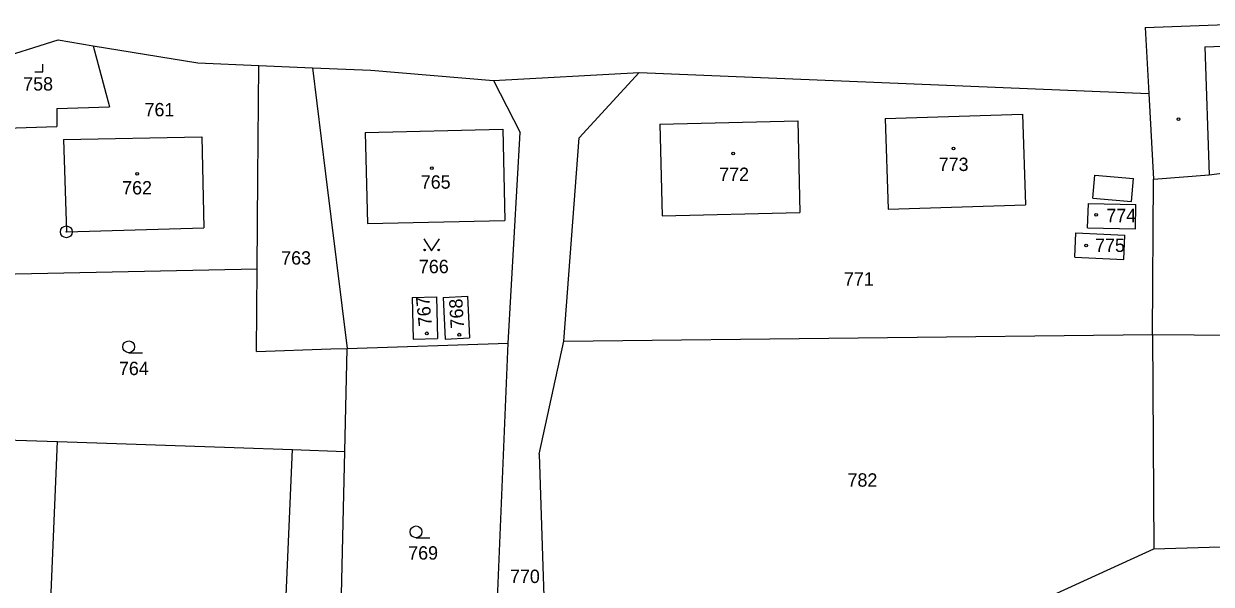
# Model space of a CAD drawing. Extents: x -779596 to -776743, y -1030330 to -1024513.
# Drawn here: x -778089.5 to -777938.4, y -1025062.8 to -1024991.4 of the extents above; entities that cross this region are included whole.
import ezdxf

# ---------------------------------------------------------------- set-up
doc = ezdxf.new("R2010")
doc.units = 0
for name, color, linetype in [('hranice parcel', 7, 'Continuous'), ('hranice vnitřní', 7, 'Continuous'), ('kultura', 7, 'Continuous'), ('Kód', 7, 'Continuous'), ('č_pacel stav_', 7, 'Continuous'), ('č_parcel poz_', 7, 'Continuous')]:
    doc.layers.add(name, color=color, linetype=linetype)

msp = doc.modelspace()

# ---------------------------------------------------------------- linework, layer by layer
at = {"layer": 'hranice parcel'}
for points in [[(-777946.82, -1024991.9), (-777934.22, -1024991.43)], [(-777946.82, -1024991.9), (-777946.37, -1025000.32)], [(-778093.81, -1024996.18), (-778085.15, -1024993.48)], [(-778085.15, -1024993.48), (-778080.71, -1024994.22)], [(-778080.71, -1024994.22), (-778067.37, -1024996.42)], [(-778080.71, -1024994.22), (-778078.6, -1025002)], [(-778067.37, -1024996.42), (-778059.62, -1024996.75)], [(-778059.74, -1025011.01), (-778059.62, -1024996.75)], [(-778059.62, -1024996.75), (-778052.78, -1024997.04)], [(-778052.78, -1024997.04), (-778045.34, -1024997.35)], [(-778052.78, -1024997.04), (-778051.11, -1025010.51)], [(-778045.34, -1024997.35), (-778029.75, -1024998.66)], [(-778029.75, -1024998.66), (-778011.2, -1024997.65)], [(-778018.85, -1025005.96), (-778011.2, -1024997.65)], [(-778011.2, -1024997.65), (-777946.37, -1025000.32)], [(-778029.75, -1024998.66), (-778026.36, -1025005.29)], [(-777946.37, -1025000.32), (-777945.78, -1025011.19)], [(-778085.3, -1025002.2), (-778078.6, -1025002)], [(-778085.3, -1025002.2), (-778085.3, -1025004.5)], [(-778008.58, -1025004.22), (-777991.03, -1025003.8)], [(-778008.58, -1025004.22), (-778008.3, -1025015.87)], [(-777991.03, -1025003.8), (-777990.75, -1025015.45)], [(-777979.91, -1025003.49), (-777962.42, -1025002.93)], [(-777979.91, -1025003.49), (-777979.54, -1025015.04)], [(-777962.42, -1025002.93), (-777962.05, -1025014.49)], [(-778091.8, -1025004.7), (-778085.3, -1025004.5)], [(-778084.45, -1025006.17), (-778066.85, -1025005.82)], [(-778066.85, -1025005.82), (-778066.62, -1025017.38)], [(-778046.07, -1025005.26), (-778028.56, -1025004.86)], [(-778046.07, -1025005.26), (-778045.8, -1025016.87)], [(-778028.56, -1025004.86), (-778028.29, -1025016.47)], [(-778027.87, -1025032.06), (-778026.36, -1025005.29)], [(-778084.45, -1025006.17), (-778084.1, -1025017.91)], [(-778020.82, -1025031.82), (-778018.85, -1025005.96)], [(-777938.7, -1025010.66), (-777923.12, -1025008.6)], [(-778059.83, -1025022.61), (-778059.74, -1025011.01)], [(-778051.11, -1025010.51), (-778048.36, -1025032.75)], [(-777945.88, -1025030.99), (-777945.78, -1025011.19)], [(-777945.78, -1025011.19), (-777938.7, -1025010.66)], [(-777979.54, -1025015.04), (-777962.05, -1025014.49)], [(-777954.16, -1025017.4), (-777954.02, -1025014.31)], [(-777954.02, -1025014.31), (-777948.02, -1025014.44)], [(-777948.05, -1025017.53), (-777948.02, -1025014.44)], [(-778045.8, -1025016.87), (-778028.29, -1025016.47)], [(-778008.3, -1025015.87), (-777990.75, -1025015.45)], [(-778084.1, -1025017.91), (-778066.62, -1025017.38)], [(-777954.16, -1025017.4), (-777948.05, -1025017.53)], [(-777955.79, -1025021.12), (-777955.64, -1025018.03)], [(-777955.64, -1025018.03), (-777949.4, -1025018.32)], [(-777949.54, -1025021.42), (-777949.4, -1025018.32)], [(-777955.79, -1025021.12), (-777949.54, -1025021.42)], [(-778096.77, -1025023.38), (-778059.83, -1025022.61)], [(-778059.92, -1025033.12), (-778059.83, -1025022.61)], [(-778040.11, -1025026.27), (-778037, -1025026.2)], [(-778040.11, -1025026.27), (-778039.98, -1025031.56)], [(-778037, -1025026.2), (-778036.87, -1025031.48)], [(-778036.17, -1025026.26), (-778033.07, -1025026.1)], [(-778036.17, -1025026.26), (-778035.88, -1025031.56)], [(-778033.07, -1025026.1), (-778032.79, -1025031.39)], [(-778039.98, -1025031.56), (-778036.87, -1025031.48)], [(-778035.88, -1025031.56), (-778032.79, -1025031.39)], [(-778020.82, -1025031.82), (-777945.88, -1025030.99)], [(-777945.88, -1025030.99), (-777945.73, -1025058.25)], [(-777945.88, -1025030.99), (-777903.62, -1025031.31)], [(-778059.92, -1025033.12), (-778050.44, -1025032.82)], [(-778050.44, -1025032.82), (-778048.36, -1025032.75)], [(-778048.67, -1025045.85), (-778048.36, -1025032.75)], [(-778048.36, -1025032.75), (-778027.87, -1025032.06)], [(-778030, -1025082.96), (-778027.87, -1025032.06)], [(-778023.95, -1025046.2), (-778020.82, -1025031.82)], [(-778095.84, -1025044.24), (-778085.23, -1025044.6)], [(-778090.68, -1025175.2), (-778085.23, -1025044.6)], [(-778085.23, -1025044.6), (-778062.76, -1025045.37)], [(-778063.31, -1025229.66), (-778055.33, -1025045.62)], [(-778062.76, -1025045.37), (-778055.33, -1025045.62)], [(-778055.33, -1025045.62), (-778048.67, -1025045.85)], [(-778049.53, -1025082.22), (-778048.67, -1025045.85)], [(-778023.95, -1025046.2), (-778023.42, -1025061.76)], [(-777965.56, -1025067.32), (-777945.73, -1025058.25)], [(-777945.73, -1025058.25), (-777933.03, -1025057.86)], [(-778023.42, -1025061.76), (-778023.12, -1025070.61)]]:
    msp.add_lwpolyline(points, dxfattribs=at)
at = {"layer": 'hranice vnitřní'}
for points in [[(-777939.24, -1024994.36), (-777933.55, -1024994.14)], [(-777939.24, -1024994.36), (-777938.7, -1025010.66)], [(-777953.49, -1025013.62), (-777953.24, -1025010.68)], [(-777953.24, -1025010.68), (-777948.31, -1025011.11)], [(-777948.56, -1025014.05), (-777948.31, -1025011.11)], [(-777953.49, -1025013.62), (-777948.56, -1025014.05)]]:
    msp.add_lwpolyline(points, dxfattribs=at)
at = {"layer": 'kultura'}
for points in [[(-778088.1, -1024997.57), (-778087.1, -1024997.57), (-778087.1, -1024996.57)], [(-778038.62, -1025018.81), (-778037.62, -1025020.31), (-778036.62, -1025018.81)], [(-778076.16, -1025033.29), (-778074.41, -1025033.29)], [(-778039.6, -1025056.84), (-778037.85, -1025056.84)]]:
    msp.add_lwpolyline(points, dxfattribs=at)
for centre, radius in [((-777942.6, -1025003.57), 0.175), ((-777971.22, -1025007.29), 0.175), ((-777999.24, -1025007.93), 0.175), ((-778075.1, -1025010.53), 0.175), ((-778037.59, -1025009.81), 0.175), ((-777953.07, -1025015.75), 0.175), ((-777954.33, -1025019.65), 0.175), ((-778038.52, -1025020.21), 0.1), ((-778036.72, -1025020.21), 0.1), ((-778038.22, -1025030.83), 0.175), ((-778034.1, -1025031), 0.175), ((-778076.16, -1025032.54), 0.75), ((-778039.6, -1025056.09), 0.75)]:
    msp.add_circle(centre, radius, dxfattribs=at)
at = {"layer": 'Kód'}
for radius in [0.75, 0.032]:
    msp.add_circle((-778084.1, -1025017.91), radius, dxfattribs=at)

# ---------------------------------------------------------------- texts
at = {"layer": 'č_pacel stav_'}
for s, p in [('758', (-778089.59, -1024999.93)), ('773', (-777973.1, -1025010.17)), ('772', (-778001.03, -1025011.44)), ('762', (-778077, -1025013.15)), ('765', (-778039, -1025012.42)), ('774', (-777951.77, -1025016.68)), ('775', (-777953.2, -1025020.47))]:
    msp.add_text(s, height=1.7, dxfattribs=at).set_placement(p)
for s, rotation, p in [('767', 95.80076, (-778037.559, -1025029.832)), ('768', 93.40074, (-778033.491, -1025030.153))]:
    msp.add_text(s, height=1.7, rotation=rotation, dxfattribs=at).set_placement(p)
at = {"layer": 'č_parcel poz_'}
for s, p in [('761', (-778074.15, -1025003.21)), ('763', (-778056.76, -1025022.08)), ('766', (-778039.24, -1025023.17)), ('771', (-777985.16, -1025024.77)), ('764', (-778077.41, -1025036.14)), ('782', (-777984.7, -1025050.34)), ('769', (-778040.6, -1025059.62)), ('770', (-778027.65, -1025062.6))]:
    msp.add_text(s, height=1.7, dxfattribs=at).set_placement(p)

doc.saveas('drawing.dxf')
